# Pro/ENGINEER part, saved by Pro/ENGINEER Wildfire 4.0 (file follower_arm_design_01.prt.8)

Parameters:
  METRIC = "NO"

Other parameters: PITCH, DRILL_DIAMETER, THREAD_DIAMETER, THREADS_PER_INCH, THREAD_DEPTH, THREAD_LENGTH, DRILL_POINT_ANGLE, DRILL_DEPTH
